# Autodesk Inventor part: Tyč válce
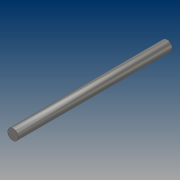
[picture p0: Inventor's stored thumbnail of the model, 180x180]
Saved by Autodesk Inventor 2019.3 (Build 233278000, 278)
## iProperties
Created: 2019-03
Part Number: Tyč válce
Material: Ocel, legovaná
Document SubType Name: Modeling
Designer: B-hon
Density: 7.73 g/cm^3
Appearance: Pololeštěná
Author: B-hon
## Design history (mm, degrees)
sketch "Náčrt1"
  geometry: C1 r 7.5 at (0, 0); 1 further point
  constraints: 1 centre point, 1 coincident
  dimensions: "d0" = 15 diameter of C1
extrude "Vysunutí1" new body sketch "Náčrt1" distance "d1" = 220; taper "d2" = 0 deg
node "Těleso1"
